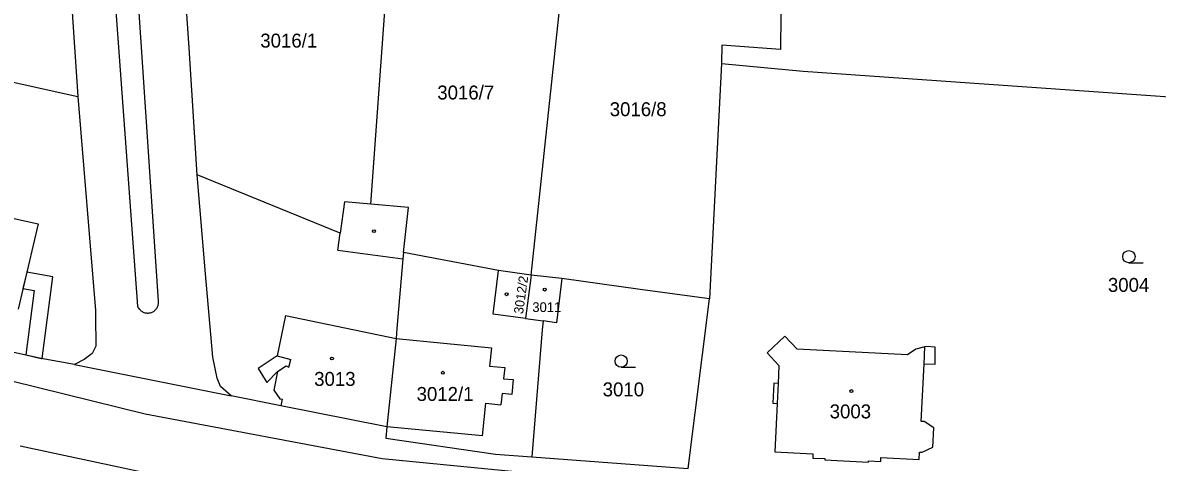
# Model space of a CAD drawing. Extents: x -869103 to -863415, y -1015889 to -1012477.
# Drawn here: x -866487.7 to -866349.1, y -1014203.9 to -1014150.2 of the extents above; entities that cross this region are included whole.
import ezdxf

# ---------------------------------------------------------------- set-up
doc = ezdxf.new("R2010")
doc.units = 0
for name, color, linetype in [('Hranice parcel', 7, 'Continuous'), ('Parcelní čísla', 7, 'Continuous'), ('Vnitřní kresba', 7, 'Continuous'), ('Věcná břemena k části', 7, 'Continuous'), ('Značky budov', 7, 'Continuous'), ('Značky kultur', 7, 'Continuous')]:
    doc.layers.add(name, color=color, linetype=linetype)

msp = doc.modelspace()

# ---------------------------------------------------------------- linework, layer by layer
at = {"layer": 'Hranice parcel'}
for p, q in [((-866485.07, -1014098.5), (-866480.97, -1014159.17)), ((-866425.6, -1014181), (-866421.77, -1014145.32)), ((-866402.32, -1014155.15), (-866403.79, -1014183.89)), ((-866489.24, -1014157.37), (-866480.97, -1014159.17)), ((-866465.39, -1014180.85), (-866466.41, -1014168.77)), ((-866425.6, -1014181), (-866429.58, -1014180.42)), ((-866425.6, -1014181), (-866426.26, -1014186.31)), ((-866421.83, -1014181.4), (-866425.6, -1014181)), ((-866406.4, -1014204.62), (-866403.79, -1014183.89)), ((-866426.26, -1014186.31), (-866424.13, -1014186.6)), ((-866481.38, -1014191.91), (-866462.25, -1014195.75)), ((-866456.16, -1014196.97), (-866462.25, -1014195.75)), ((-866443.23, -1014199.52), (-866456.16, -1014196.97)), ((-866425.49, -1014203.2), (-866406.4, -1014204.62))]:
    msp.add_line(p, q, dxfattribs=at)
for points in [[(-866466.41, -1014168.77), (-866467.37, -1014153.26), (-866468.58, -1014135.45)], [(-866445.17, -1014172.33), (-866442.57, -1014136.33), (-866432.22, -1014137.08), (-866426.43, -1014143.47)], [(-866395.02, -1014139.77), (-866395.02, -1014144.98), (-866395.11, -1014153.45), (-866402.27, -1014152.93), (-866402.32, -1014155.15)], [(-866402.32, -1014155.15), (-866392.36, -1014156.1), (-866346.96, -1014159.28), (-866306.92, -1014162.51)], [(-866480.97, -1014159.17), (-866478.82, -1014185.31), (-866478.8, -1014186)], [(-866445.17, -1014172.33), (-866448.39, -1014172.04), (-866448.91, -1014175.9), (-866466.41, -1014168.77)], [(-866564.4, -1014173.04), (-866551.48, -1014178.53), (-866472.75, -1014197.95), (-866443.8, -1014203.39), (-866405.07, -1014207.18), (-866319.44, -1014210.83), (-866244.9, -1014215.2), (-866146.71, -1014221.41), (-866140.03, -1014222.02), (-866096, -1014224.25), (-866069.13, -1014227.25), (-866022.19, -1014235.66), (-865901.45, -1014259.75)], [(-866441.17, -1014178.23), (-866440.56, -1014172.74), (-866445.17, -1014172.33)], [(-866441.17, -1014178.23), (-866441.27, -1014179.03), (-866441.99, -1014187.51), (-866442.09, -1014188.74), (-866443.23, -1014199.52)], [(-866429.58, -1014180.42), (-866435.17, -1014179.37), (-866441.17, -1014178.23)], [(-866481.38, -1014191.91), (-866485.44, -1014191.17), (-866523.17, -1014182.91), (-866527.08, -1014181.39)], [(-866462.25, -1014195.75), (-866463.56, -1014194.59), (-866463.97, -1014193.61), (-866464.49, -1014191.04), (-866465.39, -1014180.85)], [(-866426.26, -1014186.31), (-866430.24, -1014185.77), (-866429.58, -1014180.42)], [(-866421.83, -1014181.4), (-866422.48, -1014186.82), (-866424.13, -1014186.6)], [(-866403.79, -1014183.89), (-866412.24, -1014182.77), (-866421.83, -1014181.4)], [(-866478.8, -1014186), (-866478.76, -1014189.68), (-866479.24, -1014190.57), (-866480.19, -1014191.31), (-866481.38, -1014191.91)], [(-866424.13, -1014186.6), (-866424.22, -1014187.69), (-866425.49, -1014203.2)], [(-866389.68, -1014203.42), (-866389.69, -1014203.57), (-866384.36, -1014203.85), (-866384.35, -1014203.7), (-866382.86, -1014203.78), (-866382.84, -1014203.28), (-866378.15, -1014203.52), (-866378.13, -1014202.62), (-866377.81, -1014202.61), (-866376.48, -1014202.02), (-866376.37, -1014199.64), (-866377.55, -1014198.89), (-866377.94, -1014198.87), (-866377.57, -1014191.83), (-866376.19, -1014191.86), (-866376.19, -1014189.81), (-866377.24, -1014189.73), (-866377.46, -1014189.78), (-866378.59, -1014190.03), (-866379.59, -1014190.76), (-866393.07, -1014190.05), (-866394.57, -1014188.45), (-866396.73, -1014190.5), (-866395.3, -1014192.03), (-866395.41, -1014194.25), (-866395.93, -1014194.22), (-866396.05, -1014196.65), (-866395.53, -1014196.67), (-866395.82, -1014202.6), (-866391.14, -1014202.84), (-866391.17, -1014203.35), (-866389.68, -1014203.42)], [(-866443.23, -1014199.52), (-866443.32, -1014200.93), (-866429.94, -1014202.87), (-866425.49, -1014203.2)]]:
    msp.add_lwpolyline(points, dxfattribs=at)
at = {"layer": 'Vnitřní kresba'}
for p, q in [((-866478.99, -1014112.53), (-866473.68, -1014184.79)), ((-866471.12, -1014184.19), (-866475.94, -1014112.34)), ((-866493.35, -1014173.07), (-866485.82, -1014174.76)), ((-866485.82, -1014174.76), (-866488.27, -1014185.17)), ((-866449.21, -1014177.96), (-866448.91, -1014175.9)), ((-866449.21, -1014177.96), (-866441.27, -1014179.03)), ((-866455.61, -1014185.94), (-866456.6, -1014190.88)), ((-866455.61, -1014185.94), (-866442.09, -1014188.74)), ((-866442.09, -1014188.74), (-866430.44, -1014189.9)), ((-866430.44, -1014189.9), (-866430.66, -1014192.12)), ((-866377.57, -1014191.83), (-866377.46, -1014189.78)), ((-866456.6, -1014190.88), (-866458.93, -1014192.4)), ((-866456.6, -1014190.88), (-866454.93, -1014191.3)), ((-866455.18, -1014192.25), (-866454.93, -1014191.3)), ((-866458.93, -1014192.4), (-866457.88, -1014194.1)), ((-866456.56, -1014192.79), (-866455.5, -1014192.07)), ((-866455.5, -1014192.07), (-866455.18, -1014192.25)), ((-866430.66, -1014192.12), (-866428.81, -1014192.3)), ((-866428.81, -1014192.3), (-866428.95, -1014193.66)), ((-866457.88, -1014194.1), (-866456.56, -1014192.79)), ((-866456.56, -1014192.79), (-866457.01, -1014195.07)), ((-866428.95, -1014193.66), (-866427.78, -1014193.77)), ((-866427.78, -1014193.77), (-866427.96, -1014195.6)), ((-866457.01, -1014195.07), (-866456.3, -1014196.13)), ((-866429.13, -1014195.48), (-866429.27, -1014196.83)), ((-866427.96, -1014195.6), (-866429.13, -1014195.48)), ((-866395.41, -1014194.25), (-866395.53, -1014196.67)), ((-866456.3, -1014196.13), (-866456, -1014196.15)), ((-866456, -1014196.15), (-866456.16, -1014196.97)), ((-866431.52, -1014200.63), (-866431.12, -1014196.65)), ((-866431.12, -1014196.65), (-866429.27, -1014196.83)), ((-866431.52, -1014200.63), (-866443.23, -1014199.52))]:
    msp.add_line(p, q, dxfattribs=at)
msp.add_lwpolyline([(-866473.68, -1014184.79), (-866473.64, -1014184.89), (-866473.59, -1014184.98), (-866473.54, -1014185.06), (-866473.48, -1014185.15), (-866473.41, -1014185.22), (-866473.33, -1014185.3), (-866473.26, -1014185.36), (-866473.17, -1014185.42), (-866473.08, -1014185.47), (-866472.99, -1014185.52), (-866472.9, -1014185.56), (-866472.8, -1014185.59), (-866472.7, -1014185.62), (-866472.6, -1014185.63), (-866472.5, -1014185.64), (-866472.39, -1014185.64), (-866472.29, -1014185.63), (-866472.19, -1014185.62), (-866472.09, -1014185.59), (-866471.99, -1014185.56), (-866471.9, -1014185.52), (-866471.8, -1014185.48), (-866471.71, -1014185.43), (-866471.63, -1014185.36), (-866471.55, -1014185.3), (-866471.48, -1014185.23), (-866471.41, -1014185.15), (-866471.35, -1014185.07), (-866471.29, -1014184.98), (-866471.25, -1014184.89), (-866471.21, -1014184.8), (-866471.17, -1014184.7), (-866471.15, -1014184.6), (-866471.13, -1014184.5), (-866471.12, -1014184.4), (-866471.11, -1014184.29), (-866471.12, -1014184.19)], dxfattribs=at)
at = {"layer": 'Věcná břemena k části'}
msp.add_lwpolyline([(-866487.23, -1014180.64), (-866487.69, -1014182.65), (-866486.31, -1014182.89), (-866487.35, -1014190.75), (-866485.44, -1014191.17), (-866485.33, -1014191.19), (-866484.02, -1014181.21)], close=True, dxfattribs=at)
msp.add_lwpolyline([(-866471.82, -1014205.37), (-866488.01, -1014201.88)], dxfattribs=at)
at = {"layer": 'Značky budov'}
for centre in [(-866444.79, -1014175.64), (-866423.92, -1014182.77), (-866428.58, -1014183.34), (-866449.92, -1014191.18), (-866436.37, -1014192.92), (-866386.45, -1014195.16)]:
    msp.add_circle(centre, 0.175, dxfattribs=at)
at = {"layer": 'Značky kultur'}
for p, q in [((-866352.53, -1014179.5), (-866350.78, -1014179.5)), ((-866414.58, -1014192.26), (-866412.83, -1014192.26))]:
    msp.add_line(p, q, dxfattribs=at)
for centre in [(-866352.53, -1014178.75), (-866414.58, -1014191.51)]:
    msp.add_circle(centre, 0.75, dxfattribs=at)

# ---------------------------------------------------------------- texts
at = {"layer": 'Parcelní čísla'}
for s, height, p in [('3016/1', 1.7, (-866458.68, -1014153.21)), ('3016/7', 1.7, (-866437.05, -1014159.55)), ('3016/8', 1.7, (-866415.98, -1014161.59)), ('3004', 1.7, (-866355.1, -1014183.05)), ('3011', 1.19, (-866425.44, -1014185.51)), ('3013', 1.7, (-866452.1, -1014194.53)), ('3010', 1.7, (-866416.84, -1014195.81)), ('3012/1', 1.7, (-866439.58, -1014196.37)), ('3003', 1.7, (-866389.1, -1014198.5))]:
    msp.add_text(s, height=height, dxfattribs=at).set_placement(p)
msp.add_text('3012/2', height=1.139, rotation=82, dxfattribs=at).set_placement((-866426.58, -1014185.8))

doc.saveas('drawing.dxf')
